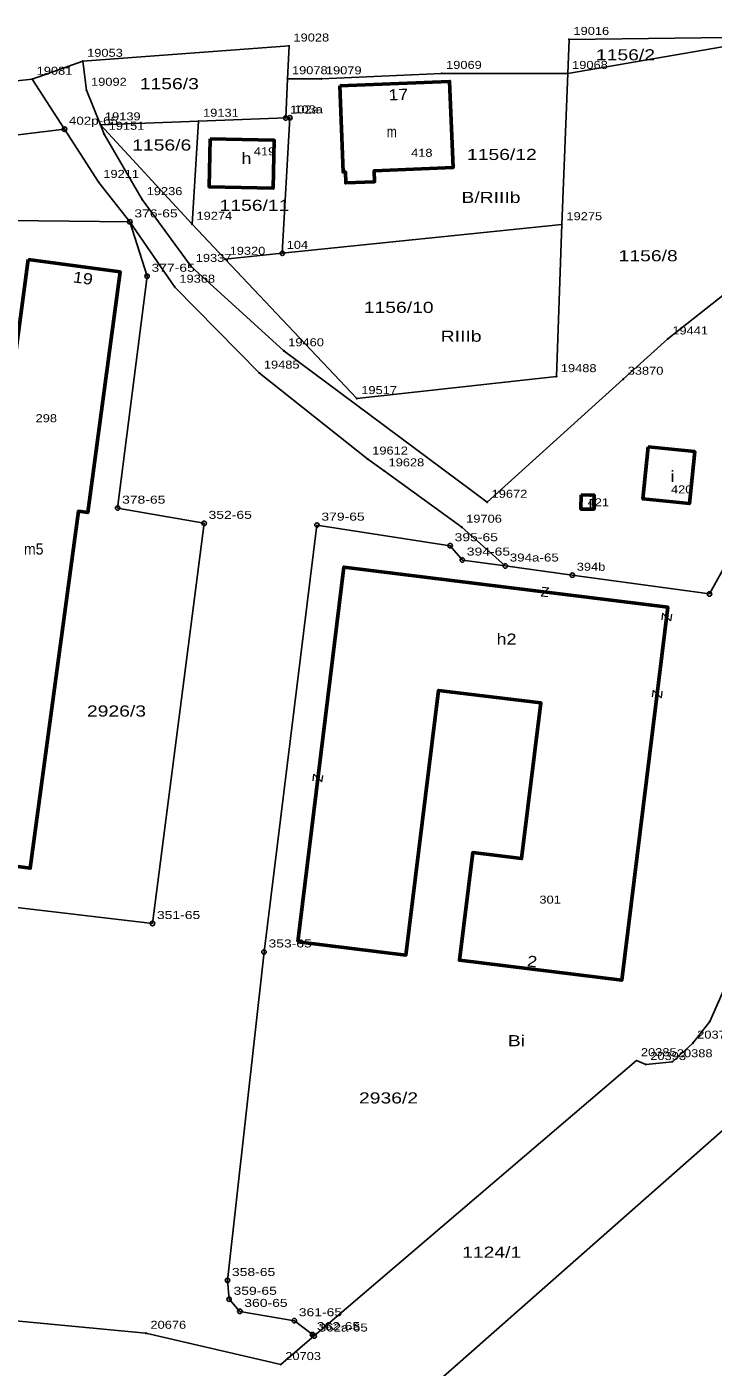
# Model space of a CAD drawing. Extents: x 4640203 to 4644676, y 5358265 to 5360852.
# Drawn here: x 4641644.7 to 4641722, y 5359260.5 to 5359411.3 of the extents above; entities that cross this region are included whole.
import ezdxf
from ezdxf.enums import TextEntityAlignment as Align

# ---------------------------------------------------------------- set-up
doc = ezdxf.new("R2010")
doc.units = 0
doc.header["$LTSCALE"] = 0.36
for name, color, linetype in [('1', 7, 'Continuous'), ('24', 7, 'Continuous'), ('26', 7, 'Continuous'), ('4', 7, 'Continuous')]:
    doc.layers.add(name, color=color, linetype=linetype)
for name, color, linetype, lineweight in [('25', 7, 'Continuous', 25), ('27', 7, 'Continuous', 25), ('3', 7, 'Continuous', 13), ('8', 7, 'Continuous', 25)]:
    doc.layers.add(name, color=color, linetype=linetype, lineweight=lineweight)

msp = doc.modelspace()

# ---------------------------------------------------------------- linework, layer by layer
at = {"layer": '25'}
for p, q in [((4641648.98, 5359399.79), (4641645.35, 5359405.41)), ((4641663.33, 5359389.1), (4641664.07, 5359400.69)), ((4641704.95, 5359389.05), (4641673.48, 5359385.83))]:
    msp.add_line(p, q, dxfattribs=at)
for points in [[(4641554.83, 5359395.58), (4641645.35, 5359405.41), (4641651.03, 5359407.43), (4641674.24, 5359409.15), (4641674.07, 5359405.47), (4641677.89, 5359405.46), (4641691.41, 5359406.07), (4641705.59, 5359406.07), (4641705.74, 5359409.89), (4641729.54, 5359410.16)], [(4641729.54, 5359410.16), (4641705.59, 5359406.07), (4641704.95, 5359389.05), (4641704.32, 5359371.96), (4641681.87, 5359369.49), (4641667.06, 5359385.16), (4641663.33, 5359389.1), (4641653.03, 5359400.28)], [(4641698.57, 5359350.66), (4641706.11, 5359349.62), (4641721.54, 5359347.51), (4641730.57, 5359363.76), (4641732.19, 5359363.34), (4641732.44, 5359363.28), (4641732.87, 5359366.38), (4641734.75, 5359371.55), (4641737.11, 5359372.7), (4641737.85, 5359374.57), (4641740.74, 5359395.07), (4641716.86, 5359376.2), (4641711.84, 5359371.67), (4641696.53, 5359357.83), (4641673.65, 5359374.87), (4641663.25, 5359384.36), (4641657.73, 5359391.87), (4641653.45, 5359399.22), (4641653.03, 5359400.28), (4641651.47, 5359404.17), (4641651.03, 5359407.43)], [(4641653.03, 5359400.28), (4641664.07, 5359400.69), (4641673.87, 5359401.05), (4641674.07, 5359405.47)], [(4641667.06, 5359385.16), (4641673.48, 5359385.83), (4641674.34, 5359401.07), (4641673.87, 5359401.05)], [(4641652.85, 5359393.81), (4641648.98, 5359399.79), (4641563.63, 5359389.41), (4641563.08, 5359378.12), (4641569.45, 5359378.17), (4641554.3, 5359293.28), (4641541.32, 5359294.66), (4641522.94, 5359296.82), (4641528.49, 5359365.85), (4641523.09, 5359366.51), (4641522.91, 5359364.74), (4641522.32, 5359358.64), (4641519.04, 5359324.57), (4641517, 5359303.33), (4641516.51, 5359298.22), (4641516.01, 5359290.58), (4641515.66, 5359285.14)], [(4641632.45, 5359389.63), (4641656.34, 5359389.37), (4641652.85, 5359393.81)], [(4641633.54, 5359266.69), (4641658.15, 5359264.36), (4641673.32, 5359260.84), (4641677.08, 5359264.05), (4641676.87, 5359264.21), (4641674.84, 5359265.77), (4641668.71, 5359266.82), (4641667.5, 5359268.18), (4641667.32, 5359270.3), (4641671.43, 5359307.25), (4641677.38, 5359355.26), (4641692.37, 5359352.94), (4641693.74, 5359351.33), (4641698.57, 5359350.66), (4641693.67, 5359355.03), (4641684.94, 5359361.36), (4641683.1, 5359362.69), (4641670.91, 5359372.36), (4641661.41, 5359382.02), (4641656.34, 5359389.37), (4641658.27, 5359383.25), (4641654.96, 5359357.17), (4641664.69, 5359355.46), (4641658.88, 5359310.45), (4641623.85, 5359314.56)], [(4641687.79, 5359256.12), (4641726.78, 5359290.5), (4641730.36, 5359293.55), (4641733.87, 5359294.74), (4641735.35, 5359294.79), (4641738.3, 5359294.91), (4641739.47, 5359293.58), (4641752.89, 5359279.05), (4641760.65, 5359286.33), (4641757.76, 5359289.42), (4641747.25, 5359300.92), (4641745.94, 5359302.68), (4641742.65, 5359307.45), (4641742.3, 5359308.83), (4641734.22, 5359317.84), (4641726.9, 5359324.62), (4641723.91, 5359306.72), (4641723.37, 5359303.51), (4641721.57, 5359299.42), (4641719.66, 5359296.99), (4641717.37, 5359294.9), (4641714.38, 5359294.59), (4641713.33, 5359295.02), (4641677.08, 5359264.05)]]:
    msp.add_lwpolyline(points, dxfattribs=at)
at = {"layer": '27'}
for points in [[(4641651.03, 5359407.43), (4641651.47, 5359404.17), (4641653.03, 5359400.28), (4641664.07, 5359400.69), (4641673.87, 5359401.05), (4641674.07, 5359405.47), (4641677.89, 5359405.46), (4641691.41, 5359406.07), (4641705.59, 5359406.07), (4641729.54, 5359410.16)], [(4641405.06, 5359375.76), (4641410.44, 5359376.41), (4641409.03, 5359378.02), (4641441.43, 5359382), (4641443.95, 5359382.31), (4641463.44, 5359384.76), (4641482.98, 5359386.86), (4641514.75, 5359390.44), (4641530.55, 5359392.25), (4641554.83, 5359395.58), (4641645.35, 5359405.41), (4641651.03, 5359407.43)], [(4641524.66, 5359375.48), (4641527.33, 5359385.01), (4641553.85, 5359388.23), (4641563.63, 5359389.41), (4641648.98, 5359399.79), (4641645.35, 5359405.41)], [(4641705.59, 5359406.07), (4641704.95, 5359389.05), (4641704.32, 5359371.96), (4641681.87, 5359369.49), (4641667.06, 5359385.16), (4641663.33, 5359389.1), (4641664.07, 5359400.69)], [(4641667.06, 5359385.16), (4641673.48, 5359385.83), (4641704.95, 5359389.05)], [(4641633.54, 5359266.69), (4641658.15, 5359264.36), (4641673.32, 5359260.84), (4641677.08, 5359264.05), (4641676.87, 5359264.21), (4641674.84, 5359265.77), (4641668.71, 5359266.82), (4641667.5, 5359268.18), (4641667.32, 5359270.3), (4641671.43, 5359307.25), (4641677.38, 5359355.26), (4641692.37, 5359352.94), (4641693.74, 5359351.33), (4641698.57, 5359350.66), (4641706.11, 5359349.62), (4641721.54, 5359347.51), (4641725.9, 5359355.36)], [(4641789.5, 5359255.49), (4641760.65, 5359286.33), (4641757.76, 5359289.42), (4641747.25, 5359300.92), (4641745.94, 5359302.68), (4641742.65, 5359307.45), (4641742.3, 5359308.83), (4641734.22, 5359317.84), (4641726.9, 5359324.62), (4641723.91, 5359306.72), (4641723.37, 5359303.51), (4641721.57, 5359299.42), (4641719.66, 5359296.99), (4641717.37, 5359294.9), (4641714.38, 5359294.59), (4641713.33, 5359295.02), (4641677.08, 5359264.05)], [(4641726.78, 5359290.5), (4641687.79, 5359256.12), (4641684.82, 5359253.98), (4641683.14, 5359253.28), (4641678.44, 5359251.94), (4641673.94, 5359251.91), (4641665.49, 5359252.69), (4641647.71, 5359254.34), (4641592.75, 5359259.45), (4641573.86, 5359261.2), (4641553.04, 5359263.13), (4641530.01, 5359265.27)]]:
    msp.add_lwpolyline(points, dxfattribs=at)
at = {"layer": '3'}
for p, q in [((4641702.6, 5359347.3), (4641703.46, 5359348.2)), ((4641702.72, 5359348.29), (4641703.46, 5359348.2)), ((4641702.6, 5359347.3), (4641703.34, 5359347.21)), ((4641716.26, 5359345.34), (4641716.17, 5359344.6)), ((4641716.26, 5359345.34), (4641717.16, 5359344.48)), ((4641717.25, 5359345.22), (4641717.16, 5359344.48)), ((4641715.19, 5359336.68), (4641715.1, 5359335.94)), ((4641715.19, 5359336.68), (4641716.09, 5359335.82)), ((4641716.18, 5359336.56), (4641716.09, 5359335.82)), ((4641676.96, 5359326.49), (4641677.05, 5359327.23)), ((4641677.95, 5359326.37), (4641677.05, 5359327.23)), ((4641677.95, 5359326.37), (4641678.04, 5359327.11))]:
    msp.add_line(p, q, dxfattribs=at)
at = {"layer": '3', "lineweight": 53}
for points in [[(4641679.95, 5359404.68), (4641692.31, 5359405.17), (4641692.69, 5359395.47), (4641683.82, 5359395.12), (4641683.87, 5359393.88), (4641680.63, 5359393.75), (4641680.58, 5359394.99), (4641680.33, 5359394.98)], [(4641665.38, 5359398.71), (4641672.57, 5359398.54), (4641672.44, 5359393.15), (4641665.25, 5359393.32)], [(4641644.88, 5359385.13), (4641655.25, 5359383.74), (4641651.6, 5359356.66), (4641650.54, 5359356.81), (4641645.13, 5359316.66), (4641640.11, 5359317.33), (4641640.05, 5359316.88), (4641633.87, 5359317.7), (4641635.05, 5359326.54), (4641635.7, 5359326.45), (4641639.97, 5359358.18), (4641641.25, 5359358.01)], [(4641714.65, 5359364.05), (4641719.88, 5359363.53), (4641719.29, 5359357.67), (4641714.06, 5359358.2)], [(4641707.09, 5359358.65), (4641708.56, 5359358.64), (4641708.55, 5359357.05), (4641707.08, 5359357.06)], [(4641675.23, 5359308.4), (4641680.42, 5359350.53), (4641716.85, 5359346.04), (4641711.68, 5359304.06), (4641693.41, 5359306.31), (4641694.91, 5359318.42), (4641700.41, 5359317.74), (4641702.57, 5359335.26), (4641691.06, 5359336.67), (4641687.39, 5359306.9)]]:
    msp.add_lwpolyline(points, close=True, dxfattribs=at)
at = {"layer": '8'}
for centre, radius in [((4641705.74, 5359409.89), 0.045), ((4641674.24, 5359409.15), 0.045), ((4641651.03, 5359407.43), 0.045), ((4641645.35, 5359405.41), 0.045), ((4641674.07, 5359405.47), 0.045), ((4641677.89, 5359405.46), 0.045), ((4641691.41, 5359406.07), 0.045), ((4641705.59, 5359406.07), 0.045), ((4641651.47, 5359404.17), 0.045), ((4641664.07, 5359400.69), 0.045), ((4641673.87, 5359401.05), 0.25), ((4641674.34, 5359401.07), 0.25), ((4641648.98, 5359399.79), 0.25), ((4641653.03, 5359400.28), 0.045), ((4641653.45, 5359399.22), 0.045), ((4641652.85, 5359393.81), 0.045), ((4641657.73, 5359391.87), 0.045), ((4641656.34, 5359389.37), 0.25), ((4641663.33, 5359389.1), 0.045), ((4641704.95, 5359389.05), 0.045), ((4641673.48, 5359385.83), 0.25), ((4641663.25, 5359384.36), 0.045), ((4641667.06, 5359385.16), 0.045), ((4641658.27, 5359383.25), 0.25), ((4641661.41, 5359382.02), 0.045), ((4641716.86, 5359376.2), 0.045), ((4641673.65, 5359374.87), 0.045), ((4641670.91, 5359372.36), 0.045), ((4641704.32, 5359371.96), 0.045), ((4641711.84, 5359371.67), 0.045), ((4641681.87, 5359369.49), 0.045), ((4641683.1, 5359362.69), 0.045), ((4641684.94, 5359361.36), 0.045), ((4641654.96, 5359357.17), 0.25), ((4641696.53, 5359357.83), 0.045), ((4641664.69, 5359355.46), 0.25), ((4641677.38, 5359355.26), 0.25), ((4641693.67, 5359355.03), 0.045), ((4641692.37, 5359352.94), 0.25), ((4641693.74, 5359351.33), 0.25), ((4641698.57, 5359350.66), 0.25), ((4641706.11, 5359349.62), 0.25), ((4641721.54, 5359347.51), 0.25), ((4641658.88, 5359310.45), 0.25), ((4641671.43, 5359307.25), 0.25), ((4641721.57, 5359299.42), 0.045), ((4641719.66, 5359296.99), 0.045), ((4641713.33, 5359295.02), 0.045), ((4641714.38, 5359294.59), 0.045), ((4641717.37, 5359294.9), 0.045), ((4641667.32, 5359270.3), 0.25), ((4641667.5, 5359268.18), 0.25), ((4641668.71, 5359266.82), 0.25), ((4641674.84, 5359265.77), 0.25), ((4641658.15, 5359264.36), 0.045), ((4641676.87, 5359264.21), 0.25), ((4641677.08, 5359264.05), 0.25), ((4641673.32, 5359260.84), 0.045)]:
    msp.add_circle(centre, radius, dxfattribs=at)

# ---------------------------------------------------------------- texts
at = {"layer": '1', "width": 1.2}
for s, rotation, p in [('17', 2.263, (4641686.56, 5359403.06)), ('19', 352.335, (4641650.98, 5359382.42)), ('2', 352.971, (4641701.52, 5359305.56))]:
    msp.add_text(s, height=1.25, rotation=rotation, dxfattribs=at).set_placement(p, align=Align.CENTER)
at = {"layer": '24', "width": 1.3}
for s, p in [('1156/2', (4641708.77, 5359407.53)), ('1156/3', (4641657.45, 5359404.28)), ('1156/6', (4641656.6, 5359397.38)), ('1156/12', (4641694.26, 5359396.32)), ('1156/11', (4641666.43, 5359390.6)), ('1156/8', (4641711.32, 5359384.93)), ('1156/10', (4641682.65, 5359379.12)), ('2926/3', (4641651.51, 5359333.72)), ('2936/2', (4641682.11, 5359290.2)), ('1124/1', (4641693.72, 5359272.85))]:
    msp.add_text(s, height=1.25, dxfattribs=at).set_placement(p)
at = {"layer": '26', "width": 1.3}
for s, p in [('B/RIIIb', (4641693.64, 5359391.49)), ('RIIIb', (4641691.31, 5359375.88)), ('Bi', (4641698.86, 5359296.64))]:
    msp.add_text(s, height=1.25, dxfattribs=at).set_placement(p)
at = {"layer": '4'}
for s, width, p in [('m', 0.8, (4641685.8, 5359398.88)), ('h', 1.2, (4641669.45, 5359395.89)), ('i', 1.3, (4641717.39, 5359360.12)), ('i', 1.3, (4641708.15, 5359357.24)), ('m5', 0.95, (4641645.52, 5359351.94)), ('h2', 1.2, (4641698.71, 5359341.81))]:
    msp.add_text(s, height=1.25, dxfattribs=dict(at, width=width)).set_placement(p, align=Align.CENTER)
at = {"layer": '4', "width": 1.2}
for s, p in [('419', (4641670.28, 5359396.84)), ('418', (4641687.97, 5359396.68)), ('298', (4641645.73, 5359366.83)), ('420', (4641717.21, 5359358.82)), ('421', (4641707.83, 5359357.37)), ('301', (4641702.41, 5359312.68))]:
    msp.add_text(s, height=0.9, dxfattribs=at).set_placement(p)
at = {"layer": '8'}
for s, width, p in [('19016', 1.2, (4641706.24, 5359410.39)), ('19028', 1.2, (4641674.74, 5359409.65)), ('19053', 1.2, (4641651.53, 5359407.93)), ('19081', 1.2, (4641645.85, 5359405.91)), ('19078', 1.2, (4641674.57, 5359405.97)), ('19079', 1.2, (4641678.39, 5359405.96)), ('19069', 1.2, (4641691.91, 5359406.57)), ('19068', 1.2, (4641706.09, 5359406.57)), ('19092', 1.2, (4641651.97, 5359404.67)), ('102a', 1.2, (4641674.37, 5359401.55)), ('103a', 1.2, (4641674.84, 5359401.57)), ('402p-65', 1.25, (4641649.48, 5359400.29)), ('19139', 1.2, (4641653.53, 5359400.78)), ('19131', 1.2, (4641664.57, 5359401.19)), ('19151', 1.2, (4641653.95, 5359399.72)), ('19211', 1.2, (4641653.35, 5359394.31)), ('19236', 1.2, (4641658.23, 5359392.37)), ('376-65', 1.3, (4641656.84, 5359389.87)), ('19274', 1.2, (4641663.83, 5359389.6)), ('19275', 1.2, (4641705.45, 5359389.55)), ('104', 1.2, (4641673.98, 5359386.33)), ('19337', 1.2, (4641663.75, 5359384.86)), ('19320', 1.2, (4641667.56, 5359385.66)), ('377-65', 1.3, (4641658.77, 5359383.75)), ('19368', 1.2, (4641661.91, 5359382.52)), ('19441', 1.2, (4641717.36, 5359376.7)), ('19460', 1.2, (4641674.15, 5359375.37)), ('19485', 1.2, (4641671.41, 5359372.86)), ('19488', 1.2, (4641704.82, 5359372.46)), ('33870', 1.2, (4641712.34, 5359372.17)), ('19517', 1.2, (4641682.37, 5359369.99)), ('19612', 1.2, (4641683.6, 5359363.19)), ('19628', 1.2, (4641685.44, 5359361.86)), ('378-65', 1.3, (4641655.46, 5359357.67)), ('19672', 1.2, (4641697.03, 5359358.33)), ('352-65', 1.3, (4641665.19, 5359355.96)), ('379-65', 1.3, (4641677.88, 5359355.76)), ('19706', 1.2, (4641694.17, 5359355.53)), ('395-65', 1.3, (4641692.87, 5359353.44)), ('394-65', 1.3, (4641694.24, 5359351.83)), ('394a-65', 1.25, (4641699.07, 5359351.16)), ('394b', 1.2, (4641706.61, 5359350.12)), ('351-65', 1.3, (4641659.38, 5359310.95)), ('353-65', 1.3, (4641671.93, 5359307.75)), ('20370', 1.2, (4641720.16, 5359297.49)), ('20385', 1.2, (4641713.83, 5359295.52)), ('20393', 1.2, (4641714.88, 5359295.09)), ('20388', 1.2, (4641717.87, 5359295.4)), ('358-65', 1.3, (4641667.82, 5359270.8)), ('359-65', 1.3, (4641668, 5359268.68)), ('360-65', 1.3, (4641669.21, 5359267.32)), ('361-65', 1.3, (4641675.34, 5359266.27)), ('20676', 1.2, (4641658.65, 5359264.86)), ('362-65', 1.3, (4641677.37, 5359264.71)), ('362a-65', 1.25, (4641677.58, 5359264.55)), ('20703', 1.2, (4641673.82, 5359261.34))]:
    msp.add_text(s, height=0.9, dxfattribs=dict(at, width=width)).set_placement(p)

doc.saveas('drawing.dxf')
